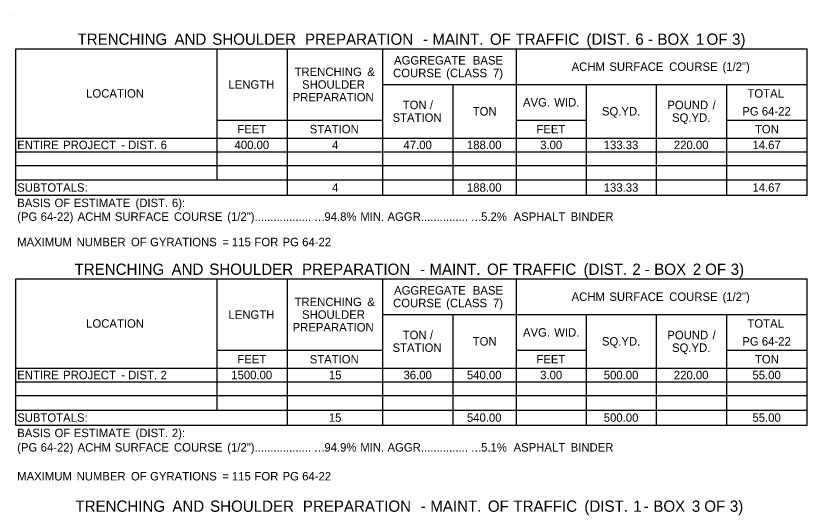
# Model space of a CAD drawing. Extents: x 542596 to 1930787, y -1948294 to 596640.
# Drawn here: x 555684 to 556245, y -1946531 to -1946176 of the extents above; entities that cross this region are included whole.
import ezdxf

# ---------------------------------------------------------------- set-up
doc = ezdxf.new("R2010")
doc.units = 0
doc.layers.add('Default', color=7, linetype='Continuous')

msp = doc.modelspace()

# ---------------------------------------------------------------- linework, layer by layer
at = {"layer": 'Default'}
for p, q in [((555683.57, -1946176.42), (555683.57, -1946176.42)), ((555683.57, -1946199.82), (556244.68, -1946199.82)), ((555683.57, -1946303.66), (555683.57, -1946199.82)), ((555826.41, -1946292.94), (555826.41, -1946199.82)), ((555876.13, -1946303.66), (555876.13, -1946199.82)), ((555943.89, -1946303.66), (555943.89, -1946199.82)), ((556038.47, -1946303.66), (556038.47, -1946199.82)), ((556244.68, -1946303.66), (556244.68, -1946199.82)), ((555943.89, -1946225.17), (556244.68, -1946225.17)), ((555993.62, -1946303.66), (555993.62, -1946225.17)), ((556088.19, -1946303.66), (556088.19, -1946225.17)), ((556137.92, -1946303.66), (556137.92, -1946225.17)), ((556187.64, -1946303.66), (556187.64, -1946225.17)), ((555826.41, -1946250.52), (555943.89, -1946250.52)), ((555876.13, -1946303.66), (555876.13, -1946250.52)), ((556038.47, -1946250.52), (556088.19, -1946250.52)), ((556038.47, -1946263.2), (556038.47, -1946250.52)), ((556088.19, -1946292.94), (556088.19, -1946250.52)), ((556187.64, -1946250.52), (556244.68, -1946250.52)), ((555683.57, -1946263.2), (555943.89, -1946263.2)), ((555826.41, -1946292.94), (555826.41, -1946263.2)), ((555943.89, -1946263.2), (556088.19, -1946263.2)), ((555943.89, -1946272.95), (555943.89, -1946263.2)), ((555993.62, -1946292.94), (555993.62, -1946263.2)), ((556088.19, -1946263.2), (556244.68, -1946263.2)), ((556137.92, -1946292.94), (556137.92, -1946263.2)), ((555683.57, -1946272.95), (555943.89, -1946272.95)), ((555876.13, -1946272.95), (555943.89, -1946272.95)), ((555943.89, -1946272.95), (556244.68, -1946272.95)), ((555683.57, -1946282.7), (556244.68, -1946282.7)), ((555683.57, -1946292.94), (555876.13, -1946292.94)), ((555683.57, -1946292.94), (555826.41, -1946292.94)), ((555826.41, -1946292.94), (556244.68, -1946292.94)), ((555943.89, -1946292.94), (556187.64, -1946292.94)), ((555943.89, -1946303.66), (555943.89, -1946292.94)), ((556187.64, -1946292.94), (556244.68, -1946292.94)), ((555683.57, -1946303.66), (556244.68, -1946303.66)), ((555683.57, -1946363.14), (556244.68, -1946363.14)), ((555683.57, -1946466.97), (555683.57, -1946363.14)), ((555826.41, -1946456.25), (555826.41, -1946363.14)), ((555876.13, -1946466.97), (555876.13, -1946363.14)), ((555943.89, -1946466.97), (555943.89, -1946363.14)), ((556038.47, -1946466.97), (556038.47, -1946363.14)), ((556244.68, -1946466.97), (556244.68, -1946363.14)), ((555943.89, -1946388.49), (556244.68, -1946388.49)), ((555993.62, -1946466.97), (555993.62, -1946388.49)), ((556088.19, -1946466.97), (556088.19, -1946388.49)), ((556137.92, -1946466.97), (556137.92, -1946388.49)), ((556187.64, -1946466.97), (556187.64, -1946388.49)), ((555826.41, -1946413.84), (555943.89, -1946413.84)), ((555876.13, -1946466.97), (555876.13, -1946413.84)), ((556038.47, -1946413.84), (556088.19, -1946413.84)), ((556038.47, -1946426.51), (556038.47, -1946413.84)), ((556088.19, -1946456.25), (556088.19, -1946413.84)), ((556187.64, -1946413.84), (556244.68, -1946413.84)), ((555683.57, -1946426.51), (555943.89, -1946426.51)), ((555826.41, -1946456.25), (555826.41, -1946426.51)), ((555943.89, -1946426.51), (556088.19, -1946426.51)), ((555943.89, -1946436.26), (555943.89, -1946426.51)), ((555993.62, -1946456.25), (555993.62, -1946426.51)), ((556088.19, -1946426.51), (556244.68, -1946426.51)), ((556137.92, -1946456.25), (556137.92, -1946426.51)), ((555683.57, -1946436.26), (556244.68, -1946436.26)), ((555683.57, -1946446.01), (556244.68, -1946446.01)), ((555943.89, -1946466.97), (555943.89, -1946446.01)), ((555683.57, -1946456.25), (556187.64, -1946456.25)), ((555683.57, -1946456.25), (556244.68, -1946456.25)), ((556187.64, -1946456.25), (556244.68, -1946456.25)), ((556187.64, -1946466.97), (556187.64, -1946456.25)), ((555683.57, -1946466.97), (556244.68, -1946466.97))]:
    msp.add_line(p, q, dxfattribs=at)

# ---------------------------------------------------------------- texts
for s, height, p in [('TRENCHING', 8, (555727.33, -1946197)), (' AND', 8, (555793.1, -1946197)), (' SHOULDER', 8, (555819.87, -1946197)), (' PREPARATION', 8, (555885.65, -1946197)), (' MAINT.', 8, (555975.97, -1946197)), (' OF', 8, (556016.8, -1946197)), (' TRAFFIC', 8, (556034.91, -1946197)), (' (DIST.', 8, (556085.25, -1946197)), (' 6', 8, (556119.87, -1946197)), (' BOX', 8, (556135.53, -1946197)), (' 1', 8, (556162.85, -1946197)), (' OF', 8, (556170.36, -1946197)), (' 3)', 8, (556188.47, -1946197)), (' -', 8, (555969.22, -1946197)), (' -', 8, (556128.79, -1946197)), ('AGGREGATE', 6, (555951.77, -1946211)), (' BASE', 6, (556005.39, -1946211)), ('TRENCHING', 6, (555881.22, -1946219.17)), ('ACHM', 6, (556077.64, -1946215.5)), (' SURFACE', 6, (556102.19, -1946215.5)), (' COURSE', 6, (556144.63, -1946215.5)), (' (1/2")', 6, (556182.41, -1946215.5)), (' &', 6, (555930.56, -1946219.17)), ('COURSE', 6, (555951.06, -1946220)), (' (CLASS', 6, (555986.51, -1946220)), (' 7)', 6, (556019.64, -1946220)), ('LENGTH', 6, (555834.36, -1946228.17)), ('SHOULDER', 6, (555886.51, -1946228.17)), ('LOCATION', 6, (555733.43, -1946234.51)), ('TOTAL', 6, (556202.32, -1946234.51)), ('PREPARATION', 6, (555879.84, -1946237.17)), ('AVG.', 6, (556043.18, -1946240.85)), (' WID.', 6, (556063.1, -1946240.85)), ('TON', 6, (555957.91, -1946242.69)), (' /', 6, (555974.94, -1946242.69)), ('TON', 6, (556007.53, -1946247.19)), ('SQ.YD.', 6, (556099.14, -1946247.19)), ('POUND', 6, (556145.52, -1946242.69)), (' /', 6, (556175.38, -1946242.69)), ('PG', 6, (556198.69, -1946247.19)), (' 64-22', 6, (556210.3, -1946247.19)), ('STATION', 6, (555950.69, -1946251.69)), ('SQ.YD.', 6, (556148.86, -1946251.69)), ('FEET', 6, (555840.64, -1946259.86)), ('STATION', 6, (555891.95, -1946259.86)), ('FEET', 6, (556052.7, -1946259.86)), ('TON', 6, (556207.65, -1946259.86)), ('ENTIRE', 6, (555684.54, -1946271.07)), (' PROJECT', 6, (555714.84, -1946271.07)), (' -', 6, (555756.13, -1946271.07)), (' DIST.', 6, (555760.99, -1946271.07)), (' 6', 6, (555784.01, -1946271.07)), ('400.00', 6, (555838.66, -1946271.07)), ('4', 6, (555907.89, -1946271.07)), ('47.00', 6, (555958.47, -1946271.07)), ('188.00', 6, (556003.43, -1946271.07)), ('3.00', 6, (556055.38, -1946271.07)), ('133.33', 6, (556100.43, -1946271.07)), ('220.00', 6, (556150.17, -1946271.07)), ('14.67', 6, (556205.87, -1946271.07)), ('SUBTOTALS:', 6, (555684.54, -1946301.3)), ('4', 6, (555907.78, -1946301.3)), ('188.00', 6, (556003.44, -1946301.3)), ('133.33', 6, (556100.42, -1946301.3)), ('14.67', 6, (556205.86, -1946301.3)), ('BASIS', 6, (555684.54, -1946312.21)), (' OF', 6, (555708.8, -1946312.21)), (' ESTIMATE', 6, (555722.39, -1946312.21)), (' (DIST.', 6, (555766.2, -1946312.21)), (' 6):', 6, (555792.01, -1946312.21)), ('(PG', 6, (555684.54, -1946321.96)), (' 64-22)', 6, (555698.92, -1946321.96)), (' ACHM', 6, (555725.17, -1946321.96)), (' SURFACE', 6, (555751.55, -1946321.96)), (' COURSE', 6, (555793.49, -1946321.96)), (' (1/2")..................', 6, (555831.25, -1946321.96)), ('94.8%', 6, (555902.35, -1946321.96)), (' MIN.', 6, (555925.59, -1946321.96)), (' AGGR...............', 6, (555944.88, -1946321.96)), ('5.2%', 6, (556013.48, -1946321.96)), ('  ASPHALT', 6, (556032.06, -1946321.96)), (' BINDER', 6, (556074.75, -1946321.96)), ('…', 6, (555894.95, -1946321.96)), ('…', 6, (556006.08, -1946321.96)), ('MAXIMUM', 6, (555684.54, -1946340)), (' NUMBER', 6, (555724.43, -1946340)), (' OF', 6, (555762.98, -1946340)), (' GYRATIONS', 6, (555776.57, -1946340)), (' =', 6, (555827.83, -1946340)), (' 115', 6, (555834.59, -1946340)), (' FOR', 6, (555850.56, -1946340)), (' PG', 6, (555870.48, -1946340)), (' 64-22', 6, (555884.39, -1946340)), ('TRENCHING', 8, (555725.23, -1946360.31)), (' AND', 8, (555791.01, -1946360.31)), (' SHOULDER', 8, (555817.77, -1946360.31)), (' PREPARATION', 8, (555883.55, -1946360.31)), (' MAINT.', 8, (555973.87, -1946360.31)), (' OF', 8, (556014.7, -1946360.31)), (' TRAFFIC', 8, (556032.81, -1946360.31)), (' (DIST.', 8, (556083.15, -1946360.31)), (' 2', 8, (556117.77, -1946360.31)), (' BOX', 8, (556133.27, -1946360.31)), (' 2', 8, (556160.59, -1946360.31)), (' OF', 8, (556169.35, -1946360.31)), (' 3)', 8, (556187.46, -1946360.31)), (' -', 8, (555967.13, -1946360.31)), (' -', 8, (556126.53, -1946360.31)), ('AGGREGATE', 6, (555951.77, -1946374.31)), (' BASE', 6, (556005.39, -1946374.31)), ('ACHM', 6, (556077.64, -1946378.81)), (' SURFACE', 6, (556102.19, -1946378.81)), (' COURSE', 6, (556144.63, -1946378.81)), (' (1/2")', 6, (556182.41, -1946378.81)), ('TRENCHING', 6, (555881.22, -1946382.49)), (' &', 6, (555930.56, -1946382.49)), ('COURSE', 6, (555951.06, -1946383.31)), (' (CLASS', 6, (555986.51, -1946383.31)), (' 7)', 6, (556019.64, -1946383.31)), ('LENGTH', 6, (555834.36, -1946391.49)), ('SHOULDER', 6, (555886.51, -1946391.49)), ('LOCATION', 6, (555733.43, -1946397.82)), ('TOTAL', 6, (556202.32, -1946397.82)), ('PREPARATION', 6, (555879.84, -1946400.49)), ('AVG.', 6, (556043.18, -1946404.16)), (' WID.', 6, (556063.1, -1946404.16)), ('TON', 6, (555957.91, -1946406)), (' /', 6, (555974.94, -1946406)), ('POUND', 6, (556145.52, -1946406)), (' /', 6, (556175.38, -1946406)), ('STATION', 6, (555950.69, -1946415)), ('TON', 6, (556007.53, -1946410.5)), ('SQ.YD.', 6, (556099.14, -1946410.5)), ('SQ.YD.', 6, (556148.86, -1946415)), ('PG', 6, (556198.69, -1946410.5)), (' 64-22', 6, (556210.3, -1946410.5)), ('FEET', 6, (555840.64, -1946423.17)), ('STATION', 6, (555891.95, -1946423.17)), ('FEET', 6, (556052.7, -1946423.17)), ('TON', 6, (556207.65, -1946423.17)), ('ENTIRE', 6, (555684.54, -1946434.39)), (' PROJECT', 6, (555714.84, -1946434.39)), (' -', 6, (555756.13, -1946434.39)), (' DIST.', 6, (555760.99, -1946434.39)), (' 2', 6, (555784.01, -1946434.39)), ('1500.00', 6, (555836.33, -1946434.39)), ('15', 6, (555905.52, -1946434.39)), ('36.00', 6, (555958.47, -1946434.39)), ('540.00', 6, (556003.43, -1946434.39)), ('3.00', 6, (556055.38, -1946434.39)), ('500.00', 6, (556100.44, -1946434.39)), ('220.00', 6, (556150.17, -1946434.39)), ('55.00', 6, (556205.88, -1946434.39)), ('SUBTOTALS:', 6, (555684.54, -1946464.61)), ('15', 6, (555905.48, -1946464.61)), ('540.00', 6, (556003.44, -1946464.61)), ('500.00', 6, (556100.45, -1946464.61)), ('55.00', 6, (556205.88, -1946464.61)), ('BASIS', 6, (555684.54, -1946475.52)), (' OF', 6, (555708.8, -1946475.52)), (' ESTIMATE', 6, (555722.39, -1946475.52)), (' (DIST.', 6, (555766.2, -1946475.52)), (' 2):', 6, (555792.01, -1946475.52)), ('(PG', 6, (555684.54, -1946485.76)), (' 64-22)', 6, (555698.92, -1946485.76)), (' ACHM', 6, (555725.17, -1946485.76)), (' SURFACE', 6, (555751.55, -1946485.76)), (' COURSE', 6, (555793.49, -1946485.76)), (' (1/2")..................', 6, (555831.25, -1946485.76)), ('94.9%', 6, (555902.35, -1946485.76)), (' MIN.', 6, (555925.59, -1946485.76)), (' AGGR...............', 6, (555944.88, -1946485.76)), ('5.1%', 6, (556013.48, -1946485.76)), ('  ASPHALT', 6, (556032.06, -1946485.76)), (' BINDER', 6, (556074.75, -1946485.76)), ('…', 6, (555894.95, -1946485.76)), ('…', 6, (556006.08, -1946485.76)), ('MAXIMUM', 6, (555684.54, -1946506.24)), (' NUMBER', 6, (555724.43, -1946506.24)), (' OF', 6, (555762.98, -1946506.24)), (' GYRATIONS', 6, (555776.57, -1946506.24)), (' =', 6, (555827.83, -1946506.24)), (' 115', 6, (555834.59, -1946506.24)), (' FOR', 6, (555850.56, -1946506.24)), (' PG', 6, (555870.48, -1946506.24)), (' 64-22', 6, (555884.39, -1946506.24)), ('TRENCHING', 8, (555725.82, -1946528.5)), (' AND', 8, (555791.59, -1946528.5)), (' SHOULDER', 8, (555818.36, -1946528.5)), (' PREPARATION', 8, (555884.14, -1946528.5)), (' MAINT.', 8, (555974.46, -1946528.5)), (' OF', 8, (556015.29, -1946528.5)), (' TRAFFIC', 8, (556033.4, -1946528.5)), (' (DIST.', 8, (556083.74, -1946528.5)), (' 1', 8, (556118.36, -1946528.5)), (' BOX', 8, (556132.61, -1946528.5)), (' 3', 8, (556159.93, -1946528.5)), (' OF', 8, (556168.76, -1946528.5)), (' 3)', 8, (556186.87, -1946528.5)), (' -', 8, (555967.71, -1946528.5)), (' -', 8, (556125.87, -1946528.5))]:
    msp.add_text(s, height=height, dxfattribs=at).set_placement(p)

doc.saveas('drawing.dxf')
